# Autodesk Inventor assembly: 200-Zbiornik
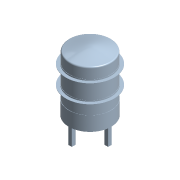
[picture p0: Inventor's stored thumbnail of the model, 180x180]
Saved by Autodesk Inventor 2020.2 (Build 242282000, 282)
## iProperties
Created: 2014-03
Part Number: 200-Zbiornik
Document SubType Name: Assembly
Designer: F.Stasiak
Catalog Web Link: www.expertbooks.pl
Manager: www.cadconsulting.pl
Company: Fabian Stasiak CAD Consulting
Author: F.Stasiak
Subject: Zbiór ćwiczeń. Autodesk Inventor 2020. Kurs Professional
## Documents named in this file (5)
- C:\2020_Kurs_Professional\R4 MES\Zbiornik\200-Zbiornik.iam
- C:\2020_Kurs_Professional\R4 MES\Zbiornik\200-000-Płaszcz.ipt
- C:\2020_Kurs_Professional\R4 MES\Zbiornik\200-002-Opaska.ipt
- C:\2020_Kurs_Professional\R4 MES\Zbiornik\200-003-Noga.ipt
- C:\2020_Kurs_Professional\R4 MES\Zbiornik\200-004-Wzmocnienie.ipt
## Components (8 placed, 4 different names)
1. 200-000-Płaszcz:1
2. 200-002-Opaska:1
3. 200-004-Wzmocnienie:1
4. 200-004-Wzmocnienie:2
5. 200-003-Noga:1
6. 200-003-Noga:2
7. 200-003-Noga:3
8. 200-003-Noga:4
